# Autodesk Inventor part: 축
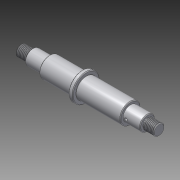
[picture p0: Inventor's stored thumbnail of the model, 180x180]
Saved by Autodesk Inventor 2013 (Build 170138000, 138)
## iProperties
Created: 2021-06
Part Number: 축
Material: 강철, 연강
Document SubType Name: Modeling
Designer: mdu
Density: 1 g/cm^3
CustomPartVersion: 1
Author: mdu
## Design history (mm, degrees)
sketch "주 스케치"
  geometry: L1 (0, 0)-(203, 0) reference; L2 (0, 0)-(0, 8); L3 (0, 8)-(17, 8); L4 (17, 8)-(17, 11); L5 (17, 11)-(42, 11); L6 (42, 11)-(42, 15); L7 (42, 15)-(90, 15); L8 (90, 15)-(90, 20); L9 (96, 20)-(96, 15); L10 (90, 20)-(96, 20); L11 (161, 15)-(161, 11); L12 (96, 15)-(161, 15); L13 (186, 11)-(186, 8); L14 (161, 11)-(186, 11); L15 (203, 8)-(203, 0); L16 (186, 8)-(203, 8)
  constraints: 32 end point, 9 horizontal, 8 vertical
  dimensions: "d3" = 16 diameter of L3 L1 (derived); "d4" = 22 diameter of L5 L1 (derived); "d5" = 30 diameter of L7 L1 (derived); "d6" = 40 diameter of L10 L1 (derived); "d7" = 30 diameter of L12 L1 (derived); "d8" = 22 diameter of L14 L1 (derived); "d9" = 16 diameter of L16 L1 (derived)
revolve "회전1" sketch "주 스케치" stored, may be unused: angle "d10" = 0 deg
chamfer "모따기1" distance "d11" = 1; stored, may be unused: second distance "d12" = 1, angle "d13" = 45 deg
chamfer "모따기2" distance "d14" = 1; stored, may be unused: second distance "d15" = 1, angle "d16" = 45 deg
node "키홈1"
chamfer "모따기3" distance "d17" = 1; stored, may be unused: second distance "d18" = 1, angle "d19" = 45 deg
fillet "모깎기1" dims "d20" = 0.3
chamfer "모따기4" distance "d21" = 1; stored, may be unused: second distance "d22" = 1, angle "d23" = 45 deg
chamfer "모따기5" distance "d24" = 1; stored, may be unused: second distance "d25" = 1, angle "d26" = 45 deg
fillet "모깎기2" dims "d27" = 0.3
chamfer "모따기6" distance "d28" = 1; stored, may be unused: second distance "d29" = 1, angle "d30" = 45 deg
chamfer "모따기7" distance "d31" = 1; stored, may be unused: second distance "d32" = 1, angle "d33" = 45 deg
node "키홈2"
chamfer "모따기8" distance "d34" = 1; stored, may be unused: second distance "d35" = 1, angle "d36" = 45 deg
sketch "스케치3"
  geometry: L1 (1, 8)-(17, 8) reference; L2 (17, -10)-(17, 10) reference; L3 (186, 10)-(186, -10) reference; L4 (186, 8)-(202, 8) reference; L5 (203, 7)-(203, -7) reference; L6 (0, 0)-(203, 0); L7 (17, 8)-(15.5, 8); L8 (15.5, 8)-(15.5, 7); L9 (15.5, 7)-(17, 7); L10 (17, 7)-(17, 8); L11 (186, 8)-(187.5, 8); L12 (187.5, 8)-(187.5, 7); L13 (187.5, 7)-(186, 7); L14 (186, 7)-(186, 8)
  constraints: 18 end point, 4 parallel, 2 horizontal, 2 perpendicular, 1 midpoint
  dimensions: "d37" = 14 diameter of L13 L6; "d39" = 1.5 distance of L12.end L13.end; "d40" = 14 diameter of L9 L6; "d41" = 1.5 distance of L8.end L9.end
revolve "회전2" sketch "스케치3" stored, may be unused: angle "d42" = 90 deg
feature "스레드1" dims "d43" = 10, "d44" = 0
feature "스레드2" dims "d45" = 10, "d46" = 0
sketch "스케치4"
  geometry: L1 (186, 7)-(186, -7) reference; L2 (186, 10)-(186, -10) reference; L3 (161, -11)-(185, -11) reference; L4 (165.225, -11)-(165.225, -9); L5 (165.225, -9)-(167.225, -11); L6 (165.225, -11)-(167.225, -11); 1 further point
  constraints: 6 end point, 2 point on line, 1 collinear, 1 perpendicular
  dimensions: "d47" = 20.77468 distance from line of L2 L4.start; "d48" = 4 diameter of L5.end L4; "d49" = 45 deg angle of L4 L5
revolve "회전3" sketch "스케치4" stored, may be unused: angle "d50" = 90 deg
node "솔리드1"
feature "iFeature3:1"
feature "iFeature3:2"
node "투영된 루프1"
other parameters: "d0" = 0, "d1" = 0, "d2" = 0
